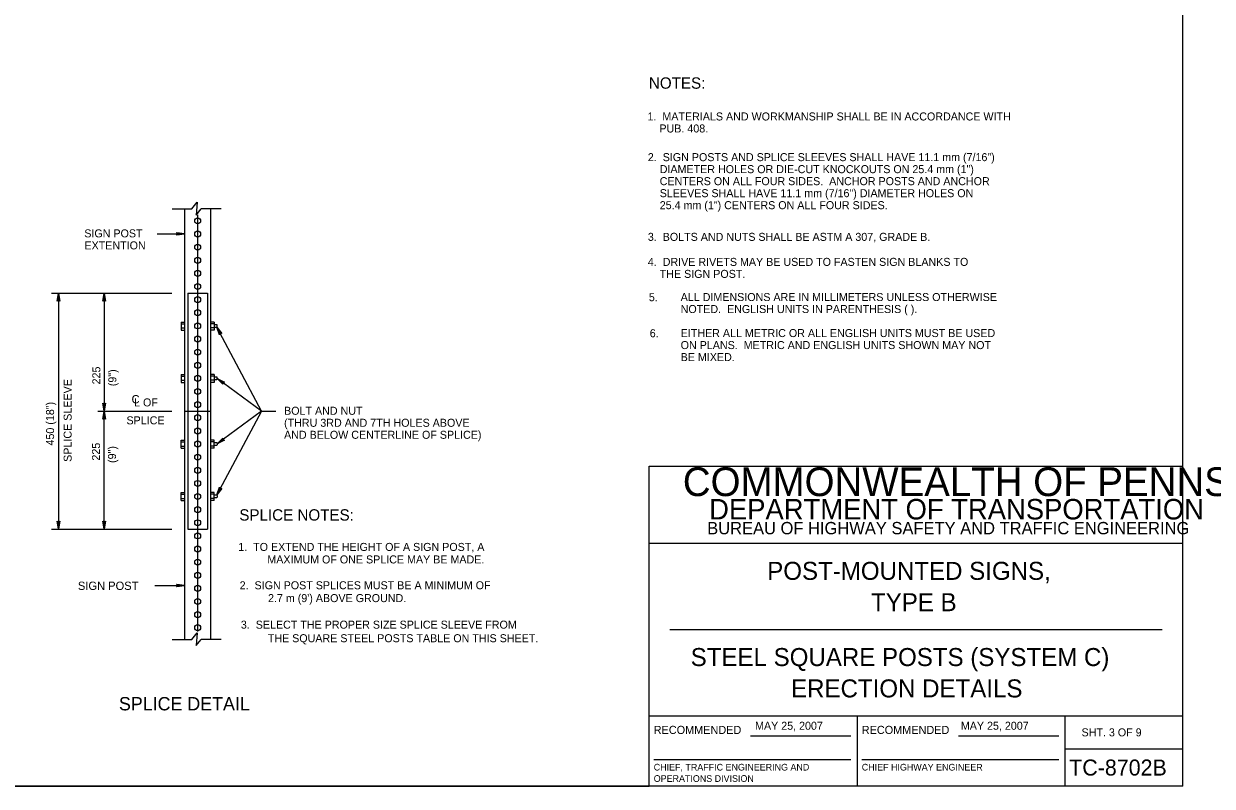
# Model space of a CAD drawing. Extents: x 644358 to 648627, y 294594 to 295782.
# Drawn here: x 646431.8 to 646877.4, y 295202.6 to 295488.4 of the extents above; entities that cross this region are included whole.
import ezdxf

# ---------------------------------------------------------------- set-up
doc = ezdxf.new("R2010")
doc.units = 0
for name, color, linetype in [('1', 7, 'Continuous'), ('2', 7, 'Continuous'), ('3', 7, 'Continuous'), ('4', 7, 'Continuous')]:
    doc.layers.add(name, color=color, linetype=linetype)

# ---------------------------------------------------------------- blocks, each defined once
blk = doc.blocks.new('RARROW')
at = {"layer": '3'}
blk.add_lwpolyline([(-2.2695, 0.285), (-2.184875, 0.12075), (0, 0), (-2.2695, 0.285), (-2.38575, 0.384625), (0, 0), (-2.183125, -0.108), (-2.262875, -0.2705), (0, 0), (-2.38575, -0.379125), (-2.262875, -0.2705)], dxfattribs=at)

msp = doc.modelspace()

# ---------------------------------------------------------------- linework, layer by layer
at = {"layer": '1'}
for p, q in [((646866.31, 295202.63), (646866.31, 295766.63)), ((646666.31, 295202.63), (646666.31, 295322.63)), ((646666.31, 295322.63), (646866.31, 295322.63)), ((646866.31, 295293.63), (646666.31, 295293.63)), ((646674.06, 295261.31), (646858.56, 295261.31)), ((646666.31, 295229), (646866.31, 295229)), ((646744.31, 295229), (646744.31, 295202.63)), ((646822.19, 295202.63), (646822.19, 295229)), ((646704.24, 295221.57), (646741.87, 295221.57)), ((646782.24, 295221.57), (646819.87, 295221.57)), ((646822.19, 295216.63), (646866.31, 295216.63)), ((646667.99, 295212.68), (646741.87, 295212.68)), ((646745.99, 295212.68), (646819.87, 295212.68)), ((646866.31, 295202.63), (646080.31, 295202.63)), ((646080.31, 295202.63), (646666.31, 295202.63))]:
    msp.add_line(p, q, dxfattribs=at)
at = {"layer": '2'}
for p, q in [((646494.83, 295419.07), (646496.83, 295421.57)), ((646496.83, 295421.57), (646496.45, 295416.69)), ((646487.45, 295419.07), (646494.83, 295419.07)), ((646492.08, 295419.07), (646492.08, 295343.19)), ((646496.45, 295416.69), (646498.33, 295419.07)), ((646505.83, 295419.07), (646498.33, 295419.07)), ((646501.95, 295343.19), (646501.95, 295419.07)), ((646496.95, 295416.82), (646496.95, 295260.57)), ((646496.95, 295414.44), (646496.95, 295414.44)), ((646496.95, 295409.57), (646496.95, 295409.57)), ((646496.95, 295404.69), (646496.95, 295404.69)), ((646496.95, 295399.69), (646496.95, 295399.69)), ((646496.95, 295394.82), (646496.95, 295394.82)), ((646493.33, 295387.41), (646500.7, 295387.41)), ((646493.33, 295387.41), (646493.33, 295298.94)), ((646496.95, 295389.94), (646496.95, 295389.94)), ((646500.7, 295387.41), (646500.7, 295298.94)), ((646496.95, 295384.94), (646496.95, 295384.94)), ((646496.95, 295380.07), (646496.95, 295380.07)), ((646490.83, 295376.57), (646490.83, 295373.57)), ((646490.83, 295376.57), (646492.08, 295376.57)), ((646490.83, 295375.95), (646492.08, 295375.95)), ((646490.83, 295374.45), (646492.08, 295374.45)), ((646490.83, 295373.57), (646492.08, 295373.57)), ((646496.95, 295375.19), (646496.95, 295375.19)), ((646503.2, 295376.57), (646501.95, 295376.57)), ((646503.2, 295375.95), (646501.95, 295375.95)), ((646503.2, 295374.45), (646501.95, 295374.45)), ((646503.2, 295373.57), (646501.95, 295373.57)), ((646503.2, 295376.57), (646503.2, 295373.57)), ((646503.2, 295375.7), (646504.2, 295375.7)), ((646503.2, 295374.7), (646504.2, 295374.7)), ((646504.33, 295375.45), (646504.2, 295375.7)), ((646504.33, 295374.82), (646504.2, 295374.7)), ((646504.33, 295374.82), (646504.33, 295375.45)), ((646496.95, 295370.19), (646496.95, 295370.19)), ((646496.95, 295365.32), (646496.95, 295365.32)), ((646496.95, 295360.32), (646496.95, 295360.32)), ((646490.83, 295356.9), (646490.83, 295353.9)), ((646490.83, 295356.9), (646492.08, 295356.9)), ((646490.83, 295356.28), (646492.08, 295356.28)), ((646490.83, 295354.78), (646492.08, 295354.78)), ((646496.95, 295355.57), (646496.95, 295355.57)), ((646503.2, 295356.9), (646501.95, 295356.9)), ((646503.2, 295356.28), (646501.95, 295356.28)), ((646503.2, 295354.78), (646501.95, 295354.78)), ((646503.2, 295356.9), (646503.2, 295353.9)), ((646503.2, 295356.03), (646504.2, 295356.03)), ((646503.2, 295355.03), (646504.2, 295355.03)), ((646504.33, 295355.78), (646504.2, 295356.03)), ((646504.33, 295355.15), (646504.2, 295355.03)), ((646504.33, 295355.15), (646504.33, 295355.78)), ((646490.83, 295353.9), (646492.08, 295353.9)), ((646496.95, 295350.57), (646496.95, 295350.57)), ((646503.2, 295353.9), (646501.95, 295353.9)), ((646492.08, 295343.19), (646492.08, 295257.57)), ((646492.08, 295343.19), (646501.95, 295343.19)), ((646496.95, 295345.57), (646496.95, 295345.57)), ((646501.95, 295257.57), (646501.95, 295343.19)), ((646496.95, 295340.82), (646496.95, 295340.82)), ((646490.83, 295329.36), (646490.83, 295332.36)), ((646490.83, 295332.36), (646492.08, 295332.36)), ((646496.95, 295335.82), (646496.95, 295335.82)), ((646503.2, 295332.36), (646501.95, 295332.36)), ((646503.2, 295329.36), (646503.2, 295332.36)), ((646490.83, 295331.74), (646492.08, 295331.74)), ((646490.83, 295330.11), (646492.08, 295330.11)), ((646490.83, 295329.36), (646492.08, 295329.36)), ((646496.95, 295330.82), (646496.95, 295330.82)), ((646503.2, 295331.74), (646501.95, 295331.74)), ((646503.2, 295330.11), (646501.95, 295330.11)), ((646503.2, 295329.36), (646501.95, 295329.36)), ((646503.2, 295331.49), (646504.2, 295331.49)), ((646503.2, 295330.49), (646504.2, 295330.49)), ((646504.33, 295331.24), (646504.2, 295331.49)), ((646504.33, 295330.61), (646504.2, 295330.49)), ((646504.33, 295331.24), (646504.33, 295330.61)), ((646496.95, 295325.94), (646496.95, 295325.94)), ((646496.95, 295321.07), (646496.95, 295321.07)), ((646496.95, 295316.07), (646496.95, 295316.07)), ((646490.83, 295309.69), (646490.83, 295312.69)), ((646490.83, 295312.69), (646492.08, 295312.69)), ((646490.83, 295312.07), (646492.08, 295312.07)), ((646490.83, 295310.44), (646492.08, 295310.44)), ((646496.95, 295311.19), (646496.95, 295311.19)), ((646503.2, 295312.69), (646501.95, 295312.69)), ((646503.2, 295312.07), (646501.95, 295312.07)), ((646503.2, 295310.44), (646501.95, 295310.44)), ((646503.2, 295309.69), (646503.2, 295312.69)), ((646503.2, 295311.82), (646504.2, 295311.82)), ((646503.2, 295310.82), (646504.2, 295310.82)), ((646504.33, 295311.57), (646504.2, 295311.82)), ((646504.33, 295310.94), (646504.2, 295310.82)), ((646504.33, 295311.57), (646504.33, 295310.94)), ((646490.83, 295309.69), (646492.08, 295309.69)), ((646496.95, 295306.32), (646496.95, 295306.32)), ((646503.2, 295309.69), (646501.95, 295309.69)), ((646496.95, 295301.44), (646496.95, 295301.44)), ((646493.33, 295298.94), (646500.7, 295298.94)), ((646496.95, 295296.44), (646496.95, 295296.44)), ((646496.95, 295291.44), (646496.95, 295291.44)), ((646496.95, 295286.69), (646496.95, 295286.69)), ((646496.95, 295281.69), (646496.95, 295281.69)), ((646496.95, 295276.69), (646496.95, 295276.69)), ((646496.95, 295271.82), (646496.95, 295271.82)), ((646496.95, 295266.94), (646496.95, 295266.94)), ((646496.95, 295262.07), (646496.95, 295262.07)), ((646487.45, 295257.57), (646494.83, 295257.57)), ((646494.83, 295257.57), (646496.83, 295260.07)), ((646496.83, 295260.07), (646496.45, 295255.32)), ((646496.45, 295255.32), (646498.33, 295257.57)), ((646505.83, 295257.57), (646498.33, 295257.57))]:
    msp.add_line(p, q, dxfattribs=at)
for centre in [(646497, 295414.52), (646497, 295409.57), (646497, 295404.65), (646497, 295399.73), (646497, 295394.82), (646497, 295389.9), (646497, 295384.95), (646497, 295380.1), (646497, 295375.15), (646497, 295370.23), (646497, 295365.31), (646497, 295360.4), (646497, 295355.48), (646497, 295350.56), (646497, 295345.65), (646497, 295340.73), (646497, 295335.78), (646497, 295330.86), (646497, 295325.94), (646497, 295321.03), (646497, 295316.11), (646497, 295311.19), (646497, 295306.27), (646497, 295301.36), (646497, 295296.44), (646497, 295291.52), (646497, 295286.61), (646497, 295281.69), (646497, 295276.77), (646497, 295271.86), (646497, 295266.94), (646497, 295262.02)]:
    msp.add_circle(centre, 1.12, dxfattribs=at)
at = {"layer": '4'}
for p, q in [((646520.99, 295343.19), (646504.2, 295374.7)), ((646520.99, 295343.19), (646504.33, 295355.47)), ((646496.95, 295343.19), (646501.95, 295343.19)), ((646520.99, 295343.19), (646504.2, 295311.82)), ((646520.99, 295343.19), (646504.33, 295330.92))]:
    msp.add_line(p, q, dxfattribs=at)
for points in [[(646481.87, 295409.64), (646492.08, 295409.64)], [(646442.25, 295387.41), (646487.33, 295387.41)], [(646444.88, 295387.41), (646444.88, 295298.94)], [(646461.95, 295387.41), (646461.95, 295343.19)], [(646459.58, 295343.19), (646487.33, 295343.19)], [(646461.95, 295298.94), (646461.95, 295343.19)], [(646520.99, 295343.19), (646526.25, 295343.19)], [(646442.25, 295298.94), (646487.33, 295298.94)], [(646480.99, 295277.82), (646492.08, 295277.82)]]:
    msp.add_lwpolyline(points, dxfattribs=at)

# ---------------------------------------------------------------- block references
at = {"layer": '2', "xscale": 1.2574347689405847, "yscale": 1.3092961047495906}
for p in [(646492.08, 295409.64), (646492.08, 295277.82)]:
    msp.add_blockref('RARROW', p, dxfattribs=at)
at = {"layer": '2'}
for p, xscale, yscale, rotation in [((646444.88, 295387.41), 1.2574347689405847, 1.3092961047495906, 89.99999999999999), ((646461.95, 295387.41), 1.2574347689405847, 1.3092961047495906, 89.99999999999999), ((646504.2, 295374.7), 1.257434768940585, 1.3092961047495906, 118.6809314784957), ((646504.33, 295355.47), 1.257434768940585, 1.3092961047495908, 144.24684404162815), ((646461.95, 295343.19), 1.2574347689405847, 1.3092961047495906, -90.00000000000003), ((646461.95, 295343.19), 1.2574347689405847, 1.3092961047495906, 89.99999999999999), ((646504.33, 295330.92), 1.2574347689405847, 1.3092961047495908, -143.77483896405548), ((646504.2, 295311.82), 1.2574347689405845, 1.3092961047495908, -117.96802497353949), ((646444.88, 295298.94), 1.2574347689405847, 1.3092961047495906, -90.00000000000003), ((646461.95, 295298.94), 1.2574347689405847, 1.3092961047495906, -90.00000000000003)]:
    msp.add_blockref('RARROW', p, dxfattribs=dict(at, xscale=xscale, yscale=yscale, rotation=rotation))

# ---------------------------------------------------------------- texts
at = {"layer": '1'}
for s, height, p in [('COMMONWEALTH OF PENNSYLVANIA', 10.7828, (646678.9, 295311.36)), ('DEPARTMENT OF TRANSPORTATION', 7.6837, (646688.76, 295302.61)), ('BUREAU OF HIGHWAY SAFETY AND TRAFFIC ENGINEERING', 4.6253, (646688.04, 295297.04)), ('POST-MOUNTED SIGNS,', 6.75, (646710.54, 295279.97)), ('TYPE B', 6.75, (646749.45, 295268.22)), ('STEEL SQUARE POSTS (SYSTEM C)', 6.75, (646681.84, 295247.66)), ('ERECTION DETAILS', 6.75, (646719.47, 295235.91)), ('RECOMMENDED', 3.048, (646667.99, 295222.2)), ('RECOMMENDED', 3.048, (646745.99, 295222.2)), ('SHT. 3 OF 9', 3, (646828.39, 295221.31)), ('TC-8702B', 6, (646823.77, 295206.63)), ('CHIEF, TRAFFIC ENGINEERING AND', 2.5, (646667.99, 295208.51)), ('CHIEF HIGHWAY ENGINEER', 2.5, (646745.99, 295208.51)), ('OPERATIONS DIVISION', 2.5, (646667.99, 295204.26))]:
    msp.add_text(s, height=height, dxfattribs=at).set_placement(p)
at = {"layer": '2'}
for s, height, p in [('SPLICE DETAIL', 5, (646467.49, 295231.05)), ('MAY 25, 2007', 3, (646705.98, 295223.79)), ('MAY 25, 2007', 3, (646783.14, 295223.79))]:
    msp.add_text(s, height=height, dxfattribs=at).set_placement(p)
at = {"layer": '4'}
for s, height, p in [('NOTES:', 4.25, (646666.18, 295464.04)), ('1.  MATERIALS AND WORKMANSHIP SHALL BE IN ACCORDANCE WITH ', 3, (646665.66, 295452.14)), ('    PUB. 408.', 3, (646665.66, 295447.64)), ('2.  SIGN POSTS AND SPLICE SLEEVES SHALL HAVE 11.1 mm (7/16")', 3, (646665.78, 295436.89)), ('    DIAMETER HOLES OR DIE-CUT KNOCKOUTS ON 25.4 mm (1")', 3, (646665.78, 295432.39)), ('    CENTERS ON ALL FOUR SIDES.  ANCHOR POSTS AND ANCHOR ', 3, (646665.78, 295427.89)), ('    SLEEVES SHALL HAVE 11.1 mm (7/16") DIAMETER HOLES ON', 3, (646665.78, 295423.39)), ('    25.4 mm (1") CENTERS ON ALL FOUR SIDES.', 3, (646665.78, 295418.89)), ('SIGN POST', 3, (646454.5, 295408.32)), ('3.  BOLTS AND NUTS SHALL BE ASTM A 307, GRADE B.', 3, (646665.78, 295407.02)), ('EXTENTION', 3, (646454.56, 295403.82)), ('4.  DRIVE RIVETS MAY BE USED TO FASTEN SIGN BLANKS TO', 3, (646665.78, 295397.64)), ('    THE SIGN POST.', 3, (646665.78, 295393.14)), ('5.', 3, (646666.16, 295384.41)), ('ALL DIMENSIONS ARE IN MILLIMETERS UNLESS OTHERWISE', 3, (646678.09, 295384.46)), ('NOTED.  ENGLISH UNITS IN PARENTHESIS ( ).', 3, (646678.09, 295379.96)), ('6.', 3, (646666.49, 295370.89)), ('EITHER ALL METRIC OR ALL ENGLISH UNITS MUST BE USED', 3, (646678.09, 295370.96)), ('ON PLANS.  METRIC AND ENGLISH UNITS SHOWN MAY NOT ', 3, (646678.09, 295366.46)), ('BE MIXED.', 3, (646678.09, 295361.96)), ('C', 3.11, (646472.22, 295346.11)), ('L OF', 3, (646473.17, 295344.97)), ('SPLICE', 3, (646470.31, 295338.25)), ('BOLT AND NUT', 3, (646529.4, 295341.84)), ('(THRU 3RD AND 7TH HOLES ABOVE', 3, (646529.4, 295337.34)), ('AND BELOW CENTERLINE OF SPLICE)', 3, (646529.4, 295332.84)), ('SPLICE NOTES:', 4.25, (646512.62, 295302.18)), ('1.  TO EXTEND THE HEIGHT OF A SIGN POST, A', 3, (646512.23, 295290.81)), (' MAXIMUM OF ONE SPLICE MAY BE MADE.', 3, (646522.01, 295286.12)), ('SIGN POST', 3.115, (646452.11, 295276.19)), ('2.  SIGN POST SPLICES MUST BE A MINIMUM OF', 3, (646512.75, 295276.44)), (" 2.7 m (9') ABOVE GROUND.", 3, (646522.26, 295271.63)), ('3.  SELECT THE PROPER SIZE SPLICE SLEEVE FROM', 3, (646513.2, 295261.68)), (' THE SQUARE STEEL POSTS TABLE ON THIS SHEET.', 3, (646522.18, 295256.59))]:
    msp.add_text(s, height=height, dxfattribs=at).set_placement(p)
for s, p in [('225', (646460.51, 295353.21)), ('SPLICE SLEEVE', (646449.75, 295324.2)), ('(9")', (646466.51, 295352.55)), ('450 (18")', (646443.17, 295330.31)), ('225', (646460.39, 295324.66)), ('(9")', (646466.4, 295323.78))]:
    msp.add_text(s, height=3, rotation=90, dxfattribs=at).set_placement(p)

doc.saveas('drawing.dxf')
